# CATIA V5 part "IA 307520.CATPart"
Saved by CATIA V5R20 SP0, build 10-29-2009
Part number: IA 307520
Revision: ANY
Definition: UNKNOWN
Nomenclature: IA 307520
Source: Unknown
Bounding box of the stored display mesh (mm): x -1.5 to 1.5, y -2.85 to 4.9, z -1.5 to 1.5
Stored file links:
  C:\Users\Utente\Desktop\IO LAVORO\3D X SITO CF\CUMSA\3D files FA\FA 053012-20\IA 307520.CATPart

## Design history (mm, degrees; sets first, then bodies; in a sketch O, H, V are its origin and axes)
Body1 "Cortar-Extruir2" (main body)
  Solid1: solid without history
